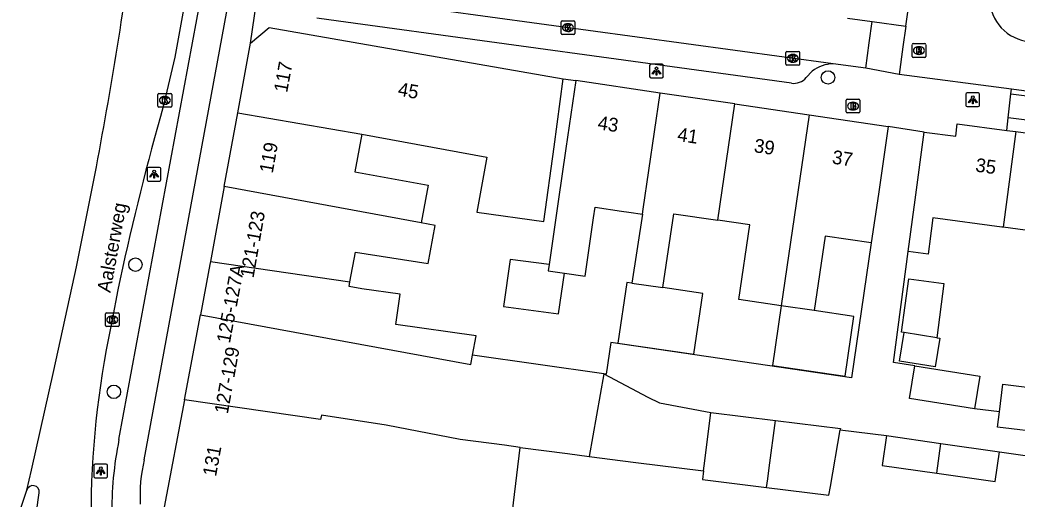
# Model space of a CAD drawing. Extents: x 161845 to 162341, y 381620 to 382158.
# Drawn here: x 161850.1 to 161922.8, y 381677.9 to 381712.9 of the extents above; entities that cross this region are included whole.
import ezdxf

# ---------------------------------------------------------------- set-up
doc = ezdxf.new("R2010")
doc.units = 0
for name, color, linetype in [('IMGEO_Boom', 7, 'Continuous'), ('IMGEO_Brandkraan', 7, 'Continuous'), ('IMGEO_Fietspad_gesloten', 7, 'Continuous'), ('IMGEO_Kolk', 7, 'Continuous'), ('IMGEO_Lichtpunt', 7, 'Continuous'), ('IMGEO_Openbare_ruimte_label', 7, 'Continuous'), ('IMGEO_OVBaan_gesloten', 7, 'Continuous'), ('IMGEO_Pand', 7, 'Continuous'), ('IMGEO_Pand_nummerreeks', 7, 'Continuous'), ('IMGEO_Rijbaan_lokaal_gesloten', 7, 'Continuous'), ('IMGEO_Rijbaan_lokaal_open', 7, 'Continuous'), ('IMGEO_Rioolput', 7, 'Continuous'), ('IMGEO_Voetpad_open', 7, 'Continuous')]:
    doc.layers.add(name, color=color, linetype=linetype)

msp = doc.modelspace()

# ---------------------------------------------------------------- linework, layer by layer
at = {"layer": 'IMGEO_Boom'}
for centre in [(161909.002, 381708.661), (161858.521, 381695.01), (161856.948, 381685.734)]:
    msp.add_circle(centre, 0.489, dxfattribs=at)
at = {"layer": 'IMGEO_Brandkraan'}
for p, q in [((161910.33, 381706.149), (161910.33, 381707.001)), ((161910.405, 381707.075), (161911.257, 381707.075)), ((161910.818, 381706.855), (161910.843, 381706.855)), ((161911.331, 381707.001), (161911.331, 381706.149)), ((161911.257, 381706.075), (161910.405, 381706.075)), ((161910.841, 381706.295), (161910.816, 381706.295))]:
    msp.add_line(p, q, dxfattribs=at)
for points in [[(161910.33, 381706.149), (161910.33, 381707.001)], [(161910.405, 381707.075), (161911.257, 381707.075)], [(161910.678, 381706.775), (161910.678, 381706.375), (161910.891, 381706.375)], [(161910.909, 381706.775), (161910.678, 381706.775)], [(161910.857, 381706.694), (161910.803, 381706.694), (161910.803, 381706.618)], [(161910.803, 381706.618), (161910.856, 381706.618)], [(161910.865, 381706.542), (161910.803, 381706.542), (161910.803, 381706.461)], [(161910.803, 381706.461), (161910.865, 381706.461)], [(161911.331, 381707.001), (161911.331, 381706.149)], [(161911.257, 381706.075), (161910.405, 381706.075)]]:
    msp.add_lwpolyline(points, dxfattribs=at)
for centre, radius, start, end in [((161910.407, 381706.999), 0.0765, 91.55205, 178.44795), ((161910.407, 381706.999), 0.0765, 91.55205, 178.44795), ((161910.858, 381706.656), 0.0379, 267.82845, 90.93552), ((161910.866, 381706.501), 0.0404, 269.87594, 90.50774), ((161910.913, 381706.63), 0.145, 59.4692, 91.53667), ((161910.938, 381706.677), 0.0922, 285.51372, 58.15012), ((161910.943, 381706.485), 0.105, 301.31148, 78.98903), ((161911.255, 381706.999), 0.0765, 1.55205, 88.44795), ((161911.255, 381706.999), 0.0765, 1.55205, 88.44795), ((161910.407, 381706.151), 0.0765, 181.55205, 268.44795), ((161910.407, 381706.151), 0.0765, 181.55205, 268.44795), ((161910.897, 381706.626), 0.251, 268.66757, 293.53466), ((161911.255, 381706.151), 0.0765, 271.55205, 358.44795), ((161911.255, 381706.151), 0.0765, 271.55205, 358.44795)]:
    msp.add_arc(centre, radius, start, end, dxfattribs=at)
for centre, major_axis, ratio, start_param, end_param in [((161910.817, 381706.575), (-0.387, 0.002), 0.722429, 4.712389, 7.853982), ((161910.842, 381706.575), (-0.39, 0.002), 0.717154, 1.570796, 4.712389)]:
    msp.add_ellipse(centre, major_axis=major_axis, ratio=ratio, start_param=start_param, end_param=end_param, dxfattribs=at)
at = {"layer": 'IMGEO_Fietspad_gesloten'}
for points in [[(161857.316, 381682.246), (161862.987, 381712.892), (161864.774, 381722.548), (161869.854, 381750), (161870.207, 381751.91), (161895.081, 381884.229), (161897.858, 381899.101), (161916.698, 382000), (161921.558, 382026.031), (161926.346, 382051.921)], [(161859.158, 381680.785), (161865.321, 381714.277)]]:
    msp.add_lwpolyline(points, dxfattribs=at)
for centre, radius, start, end in [((161883.604, 381676.943), 26.817, 168.59449, 180.62344), ((161870.183, 381678.165), 11.332, 166.6322, 183.14154)]:
    msp.add_arc(centre, radius, start, end, dxfattribs=at)
at = {"layer": 'IMGEO_Kolk'}
for p, q in [((161889.544, 381711.87), (161889.544, 381712.722)), ((161889.619, 381712.796), (161890.471, 381712.796)), ((161890.032, 381712.576), (161890.057, 381712.576)), ((161890.545, 381712.722), (161890.545, 381711.87)), ((161890.471, 381711.796), (161889.619, 381711.796)), ((161890.055, 381712.016), (161890.03, 381712.016)), ((161905.935, 381709.63), (161905.935, 381710.482)), ((161906.01, 381710.556), (161906.862, 381710.556)), ((161906.423, 381710.336), (161906.448, 381710.336)), ((161906.936, 381710.482), (161906.936, 381709.63)), ((161906.862, 381709.556), (161906.01, 381709.556)), ((161906.446, 381709.776), (161906.421, 381709.776)), ((161860.16, 381706.569), (161860.16, 381707.421)), ((161860.235, 381707.495), (161861.087, 381707.495)), ((161860.648, 381707.275), (161860.673, 381707.275)), ((161861.161, 381707.421), (161861.161, 381706.569)), ((161861.087, 381706.495), (161860.235, 381706.495)), ((161860.671, 381706.715), (161860.646, 381706.715)), ((161856.328, 381690.566), (161856.328, 381691.418)), ((161856.403, 381691.492), (161857.255, 381691.492)), ((161856.816, 381691.272), (161856.841, 381691.272)), ((161857.329, 381691.418), (161857.329, 381690.566)), ((161857.255, 381690.492), (161856.403, 381690.492)), ((161856.839, 381690.712), (161856.814, 381690.712))]:
    msp.add_line(p, q, dxfattribs=at)
for points in [[(161889.544, 381711.87), (161889.544, 381712.722)], [(161889.619, 381712.796), (161890.471, 381712.796)], [(161889.865, 381712.496), (161889.988, 381712.496), (161889.988, 381712.345), (161890.118, 381712.496), (161890.282, 381712.496), (161890.136, 381712.345), (161890.289, 381712.096), (161890.137, 381712.096), (161890.052, 381712.26), (161889.988, 381712.193), (161889.988, 381712.096), (161889.865, 381712.096), (161889.865, 381712.496)], [(161890.545, 381712.722), (161890.545, 381711.87)], [(161890.471, 381711.796), (161889.619, 381711.796)], [(161905.935, 381709.63), (161905.935, 381710.482)], [(161906.01, 381710.556), (161906.862, 381710.556)], [(161906.256, 381710.256), (161906.379, 381710.256), (161906.379, 381710.105), (161906.509, 381710.256), (161906.673, 381710.256), (161906.527, 381710.105), (161906.68, 381709.856), (161906.528, 381709.856), (161906.443, 381710.02), (161906.379, 381709.953), (161906.379, 381709.856), (161906.256, 381709.856), (161906.256, 381710.256)], [(161906.936, 381710.482), (161906.936, 381709.63)], [(161906.862, 381709.556), (161906.01, 381709.556)], [(161860.16, 381706.569), (161860.16, 381707.421)], [(161860.235, 381707.495), (161861.087, 381707.495)], [(161860.481, 381707.195), (161860.604, 381707.195), (161860.604, 381707.044), (161860.734, 381707.195), (161860.898, 381707.195), (161860.752, 381707.044), (161860.905, 381706.795), (161860.753, 381706.795), (161860.668, 381706.959), (161860.604, 381706.892), (161860.604, 381706.795), (161860.481, 381706.795), (161860.481, 381707.195)], [(161861.161, 381707.421), (161861.161, 381706.569)], [(161861.087, 381706.495), (161860.235, 381706.495)], [(161856.328, 381690.566), (161856.328, 381691.418)], [(161856.403, 381691.492), (161857.255, 381691.492)], [(161856.649, 381691.192), (161856.772, 381691.192), (161856.772, 381691.041), (161856.902, 381691.192), (161857.066, 381691.192), (161856.92, 381691.041), (161857.073, 381690.792), (161856.921, 381690.792), (161856.836, 381690.956), (161856.772, 381690.889), (161856.772, 381690.792), (161856.649, 381690.792), (161856.649, 381691.192)], [(161857.329, 381691.418), (161857.329, 381690.566)], [(161857.255, 381690.492), (161856.403, 381690.492)]]:
    msp.add_lwpolyline(points, dxfattribs=at)
for centre, start, end in [((161889.621, 381712.72), 91.55205, 178.44795), ((161889.621, 381712.72), 91.55205, 178.44795), ((161890.469, 381712.72), 1.55205, 88.44795), ((161890.469, 381712.72), 1.55205, 88.44795), ((161889.621, 381711.872), 181.55205, 268.44795), ((161889.621, 381711.872), 181.55205, 268.44795), ((161890.469, 381711.872), 271.55205, 358.44795), ((161890.469, 381711.872), 271.55205, 358.44795), ((161906.012, 381710.48), 91.55205, 178.44795), ((161906.012, 381710.48), 91.55205, 178.44795), ((161906.86, 381710.48), 1.55205, 88.44795), ((161906.86, 381710.48), 1.55205, 88.44795), ((161906.012, 381709.632), 181.55205, 268.44795), ((161906.012, 381709.632), 181.55205, 268.44795), ((161906.86, 381709.632), 271.55205, 358.44795), ((161906.86, 381709.632), 271.55205, 358.44795), ((161860.237, 381707.419), 91.55205, 178.44795), ((161860.237, 381707.419), 91.55205, 178.44795), ((161861.085, 381707.419), 1.55205, 88.44795), ((161861.085, 381707.419), 1.55205, 88.44795), ((161860.237, 381706.571), 181.55205, 268.44795), ((161860.237, 381706.571), 181.55205, 268.44795), ((161861.085, 381706.571), 271.55205, 358.44795), ((161861.085, 381706.571), 271.55205, 358.44795), ((161856.405, 381691.416), 91.55205, 178.44795), ((161856.405, 381691.416), 91.55205, 178.44795), ((161857.253, 381691.416), 1.55205, 88.44795), ((161857.253, 381691.416), 1.55205, 88.44795), ((161856.405, 381690.568), 181.55205, 268.44795), ((161856.405, 381690.568), 181.55205, 268.44795), ((161857.253, 381690.568), 271.55205, 358.44795), ((161857.253, 381690.568), 271.55205, 358.44795)]:
    msp.add_arc(centre, 0.0765, start, end, dxfattribs=at)
for centre, major_axis, ratio, start_param, end_param in [((161890.031, 381712.296), (-0.387, 0.002), 0.722429, 4.712389, 7.853982), ((161890.056, 381712.296), (-0.39, 0.002), 0.717154, 1.570796, 4.712389), ((161906.422, 381710.056), (-0.387, 0.002), 0.722429, 4.712389, 7.853982), ((161906.447, 381710.056), (-0.39, 0.002), 0.717154, 1.570796, 4.712389), ((161860.647, 381706.995), (-0.387, 0.002), 0.722429, 4.712389, 7.853982), ((161860.672, 381706.995), (-0.39, 0.002), 0.717154, 1.570796, 4.712389), ((161856.815, 381690.992), (-0.387, 0.002), 0.722429, 4.712389, 7.853982), ((161856.84, 381690.992), (-0.39, 0.002), 0.717154, 1.570796, 4.712389)]:
    msp.add_ellipse(centre, major_axis=major_axis, ratio=ratio, start_param=start_param, end_param=end_param, dxfattribs=at)
at = {"layer": 'IMGEO_Lichtpunt'}
for p, q in [((161896.002, 381709.528), (161896.002, 381708.721)), ((161896.002, 381709.528), (161896.002, 381708.721)), ((161896.904, 381709.623), (161896.096, 381709.623)), ((161896.904, 381709.623), (161896.096, 381709.623)), ((161896.998, 381708.721), (161896.998, 381709.528)), ((161896.998, 381708.721), (161896.998, 381709.528)), ((161896.096, 381708.627), (161896.904, 381708.627)), ((161896.096, 381708.627), (161896.904, 381708.627)), ((161919.055, 381707.434), (161919.055, 381706.627)), ((161919.055, 381707.434), (161919.055, 381706.627)), ((161919.957, 381707.529), (161919.149, 381707.529)), ((161919.957, 381707.529), (161919.149, 381707.529)), ((161920.051, 381706.627), (161920.051, 381707.434)), ((161920.051, 381706.627), (161920.051, 381707.434)), ((161919.149, 381706.533), (161919.957, 381706.533)), ((161919.149, 381706.533), (161919.957, 381706.533)), ((161860.28, 381702.106), (161859.472, 381702.106)), ((161860.28, 381702.106), (161859.472, 381702.106)), ((161859.378, 381702.011), (161859.378, 381701.204)), ((161859.378, 381702.011), (161859.378, 381701.204)), ((161860.374, 381701.204), (161860.374, 381702.011)), ((161860.374, 381701.204), (161860.374, 381702.011)), ((161859.472, 381701.11), (161860.28, 381701.11)), ((161859.472, 381701.11), (161860.28, 381701.11)), ((161855.487, 381680.372), (161855.487, 381679.565)), ((161855.487, 381680.372), (161855.487, 381679.565)), ((161856.389, 381680.467), (161855.581, 381680.467)), ((161856.389, 381680.467), (161855.581, 381680.467)), ((161856.483, 381679.565), (161856.483, 381680.372)), ((161856.483, 381679.565), (161856.483, 381680.372)), ((161855.581, 381679.471), (161856.389, 381679.471)), ((161855.581, 381679.471), (161856.389, 381679.471))]:
    msp.add_line(p, q, dxfattribs=at)
for points in [[(161896.376, 381709.192), (161896.415, 381709.164), (161896.227, 381708.902), (161896.189, 381708.929), (161896.376, 381709.192)], [(161896.478, 381709.144), (161896.525, 381709.144), (161896.525, 381708.822), (161896.478, 381708.822), (161896.478, 381709.144)], [(161896.588, 381709.164), (161896.626, 381709.191), (161896.813, 381708.929), (161896.774, 381708.901), (161896.588, 381709.164)], [(161919.429, 381707.098), (161919.468, 381707.07), (161919.28, 381706.808), (161919.242, 381706.835), (161919.429, 381707.098)], [(161919.531, 381707.05), (161919.578, 381707.05), (161919.578, 381706.728), (161919.531, 381706.728), (161919.531, 381707.05)], [(161919.641, 381707.07), (161919.679, 381707.097), (161919.866, 381706.835), (161919.827, 381706.807), (161919.641, 381707.07)], [(161859.752, 381701.675), (161859.791, 381701.647), (161859.603, 381701.385), (161859.565, 381701.412), (161859.752, 381701.675)], [(161859.854, 381701.627), (161859.901, 381701.627), (161859.901, 381701.305), (161859.854, 381701.305), (161859.854, 381701.627)], [(161859.964, 381701.647), (161860.002, 381701.674), (161860.189, 381701.412), (161860.15, 381701.384), (161859.964, 381701.647)], [(161855.861, 381680.036), (161855.9, 381680.008), (161855.712, 381679.746), (161855.674, 381679.773), (161855.861, 381680.036)], [(161855.963, 381679.988), (161856.01, 381679.988), (161856.01, 381679.666), (161855.963, 381679.666), (161855.963, 381679.988)], [(161856.073, 381680.008), (161856.111, 381680.035), (161856.298, 381679.773), (161856.259, 381679.745), (161856.073, 381680.008)]]:
    msp.add_lwpolyline(points, dxfattribs=at)
for centre in [(161896.501, 381709.326), (161919.554, 381707.232), (161859.877, 381701.809), (161855.986, 381680.17)]:
    msp.add_circle(centre, 0.0994, dxfattribs=at)
for centre, start, end in [((161896.096, 381709.528), 90, 180), ((161896.096, 381709.528), 90, 180), ((161896.904, 381709.528), 0, 90), ((161896.904, 381709.528), 0, 90), ((161896.096, 381708.721), 180, 270), ((161896.096, 381708.721), 180, 270), ((161896.904, 381708.721), 270, 0), ((161896.904, 381708.721), 270, 360), ((161919.149, 381707.434), 90, 180), ((161919.149, 381707.434), 90, 180), ((161919.957, 381707.434), 0, 90), ((161919.957, 381707.434), 0, 90), ((161919.149, 381706.627), 180, 270), ((161919.149, 381706.627), 180, 270), ((161919.957, 381706.627), 270, 0), ((161919.957, 381706.627), 270, 360), ((161859.472, 381702.011), 90, 180), ((161859.472, 381702.011), 90, 180), ((161860.28, 381702.011), 0, 90), ((161860.28, 381702.011), 0, 90), ((161859.472, 381701.204), 180, 270), ((161859.472, 381701.204), 180, 270), ((161860.28, 381701.204), 270, 0), ((161860.28, 381701.204), 270, 360), ((161855.581, 381680.372), 90, 180), ((161855.581, 381680.372), 90, 180), ((161856.389, 381680.372), 0, 90), ((161856.389, 381680.372), 0, 90), ((161855.581, 381679.565), 180, 270), ((161855.581, 381679.565), 180, 270), ((161856.389, 381679.565), 270, 0), ((161856.389, 381679.565), 270, 360)]:
    msp.add_arc(centre, 0.0946, start, end, dxfattribs=at)
at = {"layer": 'IMGEO_OVBaan_gesloten'}
for points in [[(161850.6, 381678.563), (161850.947, 381680.009), (161852.565, 381687.299), (161854.222, 381694.86), (161854.959, 381698.492), (161855.668, 381702.138)], [(161850.099, 381677.022), (161850.6, 381678.563)]]:
    msp.add_lwpolyline(points, dxfattribs=at)
msp.add_arc((161552.98, 381759.757), 308.123, 349.22229, 352.7665, dxfattribs=at)
at = {"layer": 'IMGEO_Pand'}
for points in [[(161866.911, 381711.167), (161868.259, 381712.301), (161889.701, 381708.562)], [(161865.976, 381706.071), (161866.911, 381711.167)], [(161875.017, 381704.529), (161884.134, 381702.846), (161883.394, 381698.839), (161888.293, 381698.163), (161889.03, 381703.608), (161889.701, 381708.562)], [(161890.618, 381708.428), (161889.894, 381703.481), (161889.338, 381699.605), (161888.672, 381695.011)], [(161896.772, 381707.527), (161890.618, 381708.428)], [(161895.475, 381698.683), (161895.528, 381699.047), (161896.772, 381707.527)], [(161902.202, 381706.732), (161896.772, 381707.527)], [(161900.96, 381698.253), (161902.202, 381706.732)], [(161902.202, 381706.732), (161907.63, 381705.938)], [(161864.991, 381700.701), (161865.976, 381706.071)], [(161865.976, 381706.071), (161875.017, 381704.529)], [(161907.63, 381705.938), (161905.591, 381692.011)], [(161907.63, 381705.938), (161913.399, 381705.093)], [(161913.399, 381705.093), (161912.675, 381700.146), (161912.155, 381696.597)], [(161916.016, 381704.682), (161918.308, 381704.376), (161918.428, 381705.281), (161922.044, 381704.799)], [(161875.017, 381704.529), (161874.51, 381701.783), (161879.861, 381700.795), (161879.355, 381698.049)], [(161914.853, 381695.968), (161915.355, 381699.726), (161916.016, 381704.682)], [(161922.703, 381704.711), (161921.775, 381697.739)], [(161922.044, 381704.799), (161922.703, 381704.711)], [(161922.703, 381704.711), (161927.871, 381704.021)], [(161864.991, 381700.701), (161863.987, 381695.233)], [(161879.355, 381698.049), (161864.991, 381700.701)], [(161889.782, 381694.378), (161891.294, 381694.159), (161891.911, 381698.416), (161892.025, 381699.201), (161893.938, 381698.913), (161894.489, 381698.831), (161895.475, 381698.683)], [(161895.475, 381698.683), (161894.712, 381693.663)], [(161896.969, 381693.332), (161897.758, 381698.721), (161900.96, 381698.253)], [(161874.156, 381693.76), (161874.552, 381695.908), (161879.868, 381695.095), (161880.378, 381697.86), (161879.355, 381698.049)], [(161905.591, 381692.011), (161902.497, 381692.464), (161903.295, 381697.911), (161900.96, 381698.253)], [(161921.775, 381697.739), (161921.674, 381697.752), (161916.648, 381698.422), (161916.395, 381696.52), (161916.368, 381696.321), (161916.295, 381695.776), (161914.853, 381695.968)], [(161926.254, 381691.882), (161923.85, 381692.203), (161924.54, 381697.37), (161924.292, 381697.403), (161923.371, 381697.526), (161921.775, 381697.739)], [(161912.155, 381696.597), (161908.799, 381697.088), (161908.004, 381691.658)], [(161863.987, 381695.233), (161863.949, 381695.025), (161863.26, 381691.359)], [(161863.987, 381695.233), (161874.156, 381693.76)], [(161888.672, 381695.011), (161885.845, 381695.38), (161885.349, 381691.956), (161889.356, 381691.434), (161889.782, 381694.378)], [(161888.672, 381695.011), (161888.605, 381694.549), (161889.782, 381694.378)], [(161883.096, 381688.415), (161883.357, 381689.827), (161877.499, 381690.634), (161877.82, 381692.85), (161875.023, 381693.255), (161874.094, 381693.426), (161874.156, 381693.76)], [(161894.712, 381693.663), (161894.341, 381693.717), (161893.688, 381689.284), (161899.219, 381688.469), (161899.874, 381692.914), (161896.969, 381693.332)], [(161894.712, 381693.663), (161896.969, 381693.332)], [(161914.551, 381690.054), (161914.363, 381690.084), (161914.883, 381693.975), (161917.451, 381693.633), (161916.923, 381689.673)], [(161905.591, 381692.011), (161904.953, 381687.65), (161910.255, 381686.874), (161910.894, 381691.235), (161908.004, 381691.658)], [(161908.004, 381691.658), (161905.591, 381692.011)], [(161862.095, 381685.158), (161863.26, 381691.359)], [(161863.26, 381691.359), (161882.969, 381687.722), (161883.096, 381688.415)], [(161916.923, 381689.673), (161917.143, 381689.638), (161916.81, 381687.563), (161914.218, 381687.979), (161914.551, 381690.054)], [(161916.923, 381689.673), (161914.551, 381690.054)], [(161892.652, 381687.039), (161883.096, 381688.415)], [(161919.686, 381684.49), (161914.939, 381685.25), (161915.322, 381687.637)], [(161915.322, 381687.637), (161920.069, 381686.876), (161919.686, 381684.49)], [(161892.652, 381687.039), (161891.585, 381681.02)], [(161892.652, 381687.039), (161895.871, 381685.342), (161896.722, 381684.941), (161900.456, 381684.217)], [(161921.498, 381684.268), (161921.745, 381686.286), (161925.448, 381685.832)], [(161862.095, 381685.158), (161860.622, 381677.32)], [(161886.558, 381681.681), (161885.412, 381681.832), (161882.189, 381682.256), (161876.798, 381683.292), (161872.074, 381684.036), (161872.016, 381683.722), (161862.095, 381685.158)], [(161899.931, 381679.961), (161900.021, 381680.69), (161900.456, 381684.217)], [(161900.456, 381684.217), (161905.186, 381683.633)], [(161925.033, 381682.715), (161921.363, 381683.165), (161921.498, 381684.268)], [(161904.526, 381678.757), (161904.611, 381679.384), (161904.721, 381680.196), (161905.186, 381683.633)], [(161905.186, 381683.633), (161909.906, 381683.05), (161909.889, 381682.955)], [(161904.526, 381678.757), (161909.064, 381678.197), (161909.172, 381678.821), (161909.889, 381682.955)], [(161913.27, 381682.538), (161912.958, 381680.354), (161916.934, 381679.797)], [(161913.27, 381682.538), (161917.232, 381681.97)], [(161916.934, 381679.797), (161917.232, 381681.97)], [(161917.232, 381681.97), (161921.491, 381681.359)], [(161885.465, 381672.502), (161885.826, 381675.533), (161886.077, 381677.646), (161886.558, 381681.681)], [(161886.558, 381681.681), (161890.01, 381681.227), (161891.585, 381681.02)], [(161891.585, 381681.02), (161894.053, 381680.695), (161894.991, 381680.572), (161899.931, 381679.961)], [(161916.934, 381679.797), (161921.181, 381679.202), (161921.491, 381681.359)], [(161899.931, 381679.961), (161899.854, 381679.334), (161904.526, 381678.757)]]:
    msp.add_lwpolyline(points, dxfattribs=at)
at = {"layer": 'IMGEO_Rijbaan_lokaal_gesloten'}
for points in [[(161863.721, 381722.825), (161861.927, 381713.087), (161861.385, 381710.143), (161860.718, 381707.24), (161860.66, 381706.996), (161860.336, 381705.821)], [(161857.237, 381693.169), (161856.828, 381690.992), (161856.388, 381688.799)], [(161851.12, 381675.59), (161851.509, 381678.364)]]:
    msp.add_lwpolyline(points, dxfattribs=at)
for centre, radius, start, end in [((162053.993, 381651.681), 201.083, 164.38075, 168.09298), ((161923.078, 381676.552), 67.805, 169.59407, 181.46627), ((161851.048, 381678.432), 0.466, 351.57311, 163.72992)]:
    msp.add_arc(centre, radius, start, end, dxfattribs=at)
at = {"layer": 'IMGEO_Rijbaan_lokaal_open'}
for points in [[(161909.378, 381709.658), (161873.668, 381714.537), (161868.939, 381715.193)], [(161914.683, 381712.406), (161915.172, 381715.818)], [(161910.432, 381712.993), (161912.231, 381712.753)], [(161911.754, 381709.336), (161912.011, 381711.179), (161912.231, 381712.753)], [(161912.231, 381712.753), (161914.683, 381712.406)], [(161914.683, 381712.406), (161914.467, 381710.894), (161914.179, 381708.883)], [(161911.754, 381709.336), (161909.378, 381709.658)], [(161914.179, 381708.883), (161911.754, 381709.336)], [(161922.367, 381707.809), (161914.179, 381708.883)], [(161925.644, 381707.379), (161922.367, 381707.809)]]:
    msp.add_lwpolyline(points, dxfattribs=at)
msp.add_arc((161923.964, 381714.443), 3.179, 180.45146, 265.39576, dxfattribs=at)
at = {"layer": 'IMGEO_Rioolput'}
for p, q in [((161915.128, 381710.201), (161915.128, 381711.053)), ((161915.203, 381711.127), (161916.055, 381711.127)), ((161915.616, 381710.907), (161915.641, 381710.907)), ((161916.129, 381711.053), (161916.129, 381710.201)), ((161916.055, 381710.127), (161915.203, 381710.127)), ((161915.639, 381710.347), (161915.614, 381710.347))]:
    msp.add_line(p, q, dxfattribs=at)
for points in [[(161915.128, 381710.201), (161915.128, 381711.053)], [(161915.203, 381711.127), (161916.055, 381711.127)], [(161915.717, 381710.825), (161915.465, 381710.827), (161915.465, 381710.427)], [(161916.129, 381711.053), (161916.129, 381710.201)], [(161916.055, 381710.127), (161915.203, 381710.127)], [(161915.465, 381710.427), (161915.589, 381710.427), (161915.589, 381710.589), (161915.6, 381710.589)], [(161915.643, 381710.746), (161915.589, 381710.746), (161915.589, 381710.665)], [(161915.589, 381710.665), (161915.641, 381710.665)], [(161915.647, 381710.56), (161915.718, 381710.427), (161915.858, 381710.427), (161915.793, 381710.553)]]:
    msp.add_lwpolyline(points, dxfattribs=at)
for centre, radius, start, end in [((161915.205, 381711.051), 0.0765, 91.55205, 178.44795), ((161915.205, 381711.051), 0.0765, 91.55205, 178.44795), ((161915.716, 381710.715), 0.109, 350.36119, 89.41601), ((161916.053, 381711.051), 0.0765, 1.55205, 88.44795), ((161916.053, 381711.051), 0.0765, 1.55205, 88.44795), ((161915.205, 381710.203), 0.0765, 181.55205, 268.44795), ((161915.205, 381710.203), 0.0765, 181.55205, 268.44795), ((161915.599, 381710.536), 0.0533, 26.02933, 88.69889), ((161915.625, 381710.854), 0.19, 274.7715, 282.96867), ((161915.649, 381710.65), 0.0964, 77.00612, 93.18647), ((161915.663, 381710.707), 0.0378, 276.66336, 79.67722), ((161915.714, 381710.715), 0.112, 277.58423, 350.98172), ((161915.698, 381710.5), 0.108, 29.51342, 73.79051), ((161916.053, 381710.203), 0.0765, 271.55205, 358.44795), ((161916.053, 381710.203), 0.0765, 271.55205, 358.44795)]:
    msp.add_arc(centre, radius, start, end, dxfattribs=at)
for centre, major_axis, ratio, start_param, end_param in [((161915.615, 381710.627), (-0.387, 0.002), 0.722429, 4.712389, 7.853982), ((161915.64, 381710.627), (-0.39, 0.002), 0.717154, 1.570796, 4.712389)]:
    msp.add_ellipse(centre, major_axis=major_axis, ratio=ratio, start_param=start_param, end_param=end_param, dxfattribs=at)
at = {"layer": 'IMGEO_Voetpad_open'}
for points in [[(161866.911, 381711.167), (161867.479, 381715.184)], [(161906.334, 381708.242), (161873.323, 381712.777), (161871.736, 381712.996)], [(161907.838, 381709.127), (161907.41, 381708.655)], [(161889.701, 381708.562), (161890.618, 381708.428)], [(161922.127, 381705.725), (161922.319, 381707.479)], [(161922.319, 381707.479), (161926.777, 381706.91), (161926.573, 381705.169), (161922.127, 381705.725)], [(161922.319, 381707.479), (161922.367, 381707.809)], [(161922.044, 381704.799), (161922.127, 381705.725)], [(161916.016, 381704.682), (161913.399, 381705.093)], [(161912.155, 381696.597), (161910.712, 381686.751), (161893.168, 381689.321), (161892.835, 381687.013), (161892.652, 381687.039)], [(161915.322, 381687.637), (161913.774, 381687.885), (161914.853, 381695.968)], [(161921.498, 381684.268), (161919.686, 381684.49)], [(161909.889, 381682.955), (161913.27, 381682.538)], [(161921.491, 381681.359), (161947.691, 381677.6), (161946.636, 381670.142)]]:
    msp.add_lwpolyline(points, dxfattribs=at)
for centre, radius, start, end in [((161909.457, 381706.932), 2.728, 91.65019, 126.39873), ((161906.506, 381709.401), 1.172, 261.54763, 320.44887)]:
    msp.add_arc(centre, radius, start, end, dxfattribs=at)

# ---------------------------------------------------------------- texts
at = {"layer": 'IMGEO_Openbare_ruimte_label'}
msp.add_text('Aalsterweg', height=1, rotation=79.63368, dxfattribs=at).set_placement((161856.692, 381692.922))
at = {"layer": 'IMGEO_Pand_nummerreeks'}
for s, rotation, p in [('117', 79.60294, (161869.576, 381707.514)), ('45', 350.10837, (161877.603, 381707.343)), ('43', 351.66919, (161892.173, 381704.886)), ('41', 351.66919, (161897.98, 381704.035)), ('119', 79.82008, (161868.524, 381701.633)), ('39', 351.67141, (161903.563, 381703.218)), ('37', 351.67141, (161909.258, 381702.384)), ('35', 352.40258, (161919.709, 381701.801)), ('121-123', 80.03074, (161867.122, 381693.99)), ('125-127A', 79.35465, (161865.403, 381689.231)), ('127-129', 79.80729, (161865.249, 381684.079)), ('131', 79.6354, (161864.39, 381679.513))]:
    msp.add_text(s, height=1, rotation=rotation, dxfattribs=at).set_placement(p)

doc.saveas('drawing.dxf')
